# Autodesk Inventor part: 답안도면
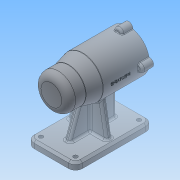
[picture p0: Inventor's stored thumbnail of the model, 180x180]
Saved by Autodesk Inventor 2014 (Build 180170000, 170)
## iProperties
Created: 2019-07
Part Number: 답안도면
Material: 일반
Document SubType Name: Modeling
Designer: net
Density: 1 g/cm^3
Appearance: 기본값
Author: net
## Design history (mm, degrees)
sketch "스케치1"
  geometry: L1 (-56, 0)-(56, 0); L2 (-56, 0)-(-50, 0); L3 (-50, 0)-(-50, 10.5); L4 (-50, 10.5)-(-47, 10.5); L5 (-47, 10.5)-(-47, 16); L6 (-47, 16)-(-43, 16); L7 (-43, 16)-(-43, 17.5); L8 (-43, 17.5)-(-25, 17.5); L9 (-25, 17.5)-(-25, 21); L10 (-25, 21)-(-13, 21); L11 (-13, 21)-(-13, 24); L12 (-13, 24)-(41, 24); L13 (41, 24)-(41, 21); L14 (41, 21)-(56, 21); L15 (56, 21)-(56, 30); L16 (56, 30)-(-11, 30); L17 (-31, 25)-(-56, 25); L18 (-56, 25)-(-56, 0); L19 (-31, 25)-(-11, 30); 2 further points
  constraints: 39 end point, 13 parallel, 3 perpendicular, 1 coincident, 1 collinear, 1 horizontal, 1 midpoint
  dimensions: "d0" = 112 distance of L1.start L1.end; "d1" = 42 diameter of L14 L1; "d2" = 60 diameter of L16 L1; "d3" = 50 diameter of L17 L1; "d4" = 48 diameter of L12 L1; "d5" = 42 diameter of L10 L1; "d6" = 35 diameter of L8 L1; "d7" = 32 diameter of L6 L1; "d9" = 21 diameter of L4 L1; "d10" = 15 distance of L13.end L14.end; "d11" = 112 distance between parallel lines of L15 L18; "d12" = 3 distance of L3.end L4.end; "d13" = 4 distance of L5.end L6.end; "d14" = 18 distance of L7.end L8.end; "d15" = 12 distance of L9.end L10.end; "d16" = 54 distance of L11.end L12.end; "d17" = 25 distance from line of L17.start L18; "d18" = 45 distance from line of L18 L16.end
revolve "회전1" sketch "스케치1" stored, may be unused: angle "d19" = 90 deg
fillet "모깎기1" dims "d20" = 10
fillet "모깎기2" dims "d21" = 3
fillet "모깎기3" dims "d22" = 3
fillet "모깎기4" dims "d23" = 0.3
fillet "모깎기5" dims "d24" = 3
node "작업 평면1"
sketch "스케치4"
  geometry: L1 (35, -56)-(-35, -56); L2 (-35, -56)-(-35, 56); L3 (-35, 56)-(35, 56); L4 (35, 56)-(35, -56); L5 (35, -56)-(-35, 56); L6 (-35, -56)-(35, 56); 1 further point
  constraints: 12 end point, 2 midpoint, 2 parallel, 1 horizontal, 1 perpendicular
  dimensions: "d26" = 70 distance of L2.end L3.end; "d27" = 112 distance of L1.end L2.end
extrude "돌출1" join sketch "스케치4" distance "d28" = 10; taper "d29" = 0 deg
fillet "모깎기6" dims "d30" = 10
sketch "스케치5"
  geometry: C1 r 3 at (-25, 46); C2 r 3 at (25, 46); C3 r 3 at (25, -46); C4 r 3 at (-25, -46); A1 r 7 centre (25, 46) between (32, 46) and (25, 53) reference; A2 r 7 centre (-25, 46) between (-25, 53) and (-32, 46) reference; A3 r 7 centre (-25, -46) between (-32, -46) and (-25, -53) reference; A4 r 7 centre (25, -46) between (25, -53) and (32, -46) reference; 1 further point
  constraints: 4 centre point, 4 coincident
  dimensions: "d32" = 6 diameter of C1; "d33" = 6 diameter of C2; "d34" = 6 diameter of C3; "d35" = 6 diameter of C4
extrude "돌출2" cut sketch "스케치5" distance "d36" = 10; taper "d37" = 0 deg
sketch "스케치6"
  geometry: L1 (-28, 4)-(28, 4); L2 (28, 4)-(28, -4); L3 (28, -4)-(-28, -4); L4 (-28, -4)-(-28, 4); L5 (-28, 4)-(28, -4); L6 (28, 4)-(-28, -4); L7 (-4, 33.5)-(4, 33.5); L8 (4, 33.5)-(4, -33.5); L9 (4, -33.5)-(-4, -33.5); L10 (-4, -33.5)-(-4, 33.5); L11 (-4, 33.5)-(4, -33.5); L12 (4, 33.5)-(-4, -33.5); 1 further point
  constraints: 24 end point, 4 midpoint, 4 parallel, 2 horizontal, 2 perpendicular
  dimensions: "d46" = 8 distance between parallel lines of L3 L1; "d47" = 56 distance between parallel lines of L4 L2; "d51" = 8 distance between parallel lines of L8 L10; "d53" = 67 distance between parallel lines of L9 L7
extrude "돌출3" join sketch "스케치6" stored distance "d54" = 10; taper "d55" = 0 deg
feature "면 기울기1" dims angle "d56" = 20 deg
feature "면 기울기2" dims angle "d57" = 10 deg
chamfer "모따기1" distance "d58" = 3; stored, may be unused: second distance "d59" = 2, angle "d60" = 45 deg
fillet "모깎기8" dims "d61" = 3
fillet "모깎기9" dims "d62" = 3
chamfer "모따기2" distance "d63" = 1; stored, may be unused: second distance "d64" = 2, angle "d65" = 45 deg
sketch "스케치7"
  geometry: C1 r 6 at (0, -30); 1 further point
  constraints: 2 vertical alignment, 1 centre point, 1 other
  dimensions: "d66" = 12 diameter of C1
extrude "돌출4" join sketch "스케치7" distance "d67" = 16; taper "d68" = 0 deg
sketch "스케치8"
  geometry: A1 r 6 centre (0, 0) between (-5.97, 0.6) and (5.97, 0.6) reference; 1 further point
  constraints: 1 coincident
hole "구멍1" sketch "스케치8" at (0, 0) diameter "d69" = 3.242; stored, may be unused: countersink angle "d73" = 90 deg, drill point angle "d75" = 118 deg; dims "d70" = 8, "d71" = 4, "d72" = 2, "d74" = 11
fillet "모깎기10" dims "d79" = 3
fillet "모깎기11" dims "d80" = 1
node "작업 평면2"
sketch "스케치9"
  geometry: L1 (56, 6.771)-(56, 29.226) reference; 2 further points
  constraints: 1 other
  dimensions: "d82" = 42 distance from line of L1 point (14, -0.137)
feature "엠보싱1" sketch "스케치9" dims "d0" = 112, "d1" = 42, "d2" = 60, "d3" = 50, "d4" = 48, "d5" = 42, "d6" = 35, "d7" = 32, "d9" = 21, "d10" = 15, "d11" = 112, "d12" = 3, "d13" = 4, "d14" = 18, "d15" = 12, "d16" = 54, "d17" = 25, "d18" = 45, "d83" = 0.5, "d84" = 0
node "솔리드1"
pattern_circular "원형 패턴1" dims angle "d77" = 360 deg
